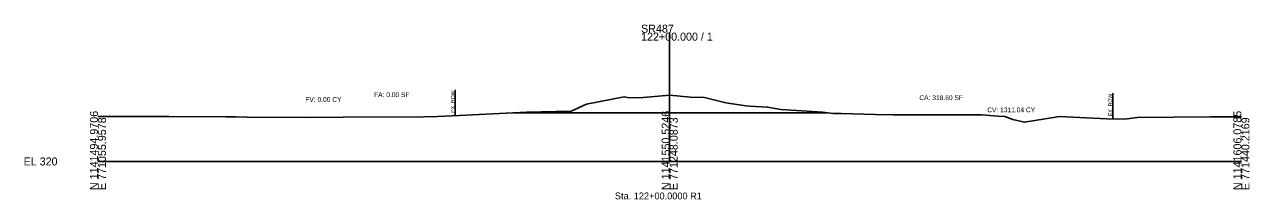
# Model space of a CAD drawing. Extents: x -26 to 5403, y -13 to 9553.
# Drawn here: x 1974.3 to 2402.8, y 1986.7 to 2047.8 of the extents above; entities that cross this region are included whole.
import ezdxf

# ---------------------------------------------------------------- set-up
doc = ezdxf.new("R2010")
doc.units = 0
for name, color, linetype in [('Default', 7, 'Continuous'), ('Draft_XS_Grid', 7, 'Continuous'), ('Draft_XS_Text', 7, 'Continuous'), ('DTM_X_GROUND', 7, 'Continuous'), ('X_ROW', 7, 'Continuous'), ('XS_CELL', 7, 'Continuous'), ('XS_M_SHAPES_EARTHWORK', 7, 'Continuous'), ('XS_P_GROUND', 7, 'Continuous'), ('XS_SHEET_EW_TX_AREA', 7, 'Continuous'), ('XS_SHEET_EW_TX_VOLUME', 7, 'Continuous')]:
    doc.layers.add(name, color=color, linetype=linetype)

msp = doc.modelspace()

# ---------------------------------------------------------------- linework, layer by layer
at = {"layer": 'Default'}
msp.add_lwpolyline([(2255.27, 2017), (2145.59, 2017)], dxfattribs=at)
at = {"layer": 'DTM_X_GROUND'}
msp.add_lwpolyline([(2000, 2015.73), (2011.96, 2015.67), (2024.75, 2015.69), (2044.77, 2015.59), (2048.4, 2015.56), (2052.22, 2015.51), (2073.02, 2015.32), (2085.71, 2015.48), (2113.96, 2015.54), (2118.81, 2015.72), (2126.35, 2016.08), (2145.19, 2016.96), (2149.92, 2017.23), (2151.07, 2017.25), (2151.34, 2017.24), (2152.46, 2017.24), (2155.1, 2017.36), (2165.52, 2017.6), (2170.92, 2020.04), (2184.07, 2022.56), (2185.86, 2022.23), (2190.68, 2022.39), (2200.11, 2023.13), (2207.28, 2022.47), (2212.23, 2022.29), (2219.66, 2020.43), (2226.67, 2019.43), (2227.9, 2019.36), (2234.26, 2018.98), (2238.93, 2018.2), (2253.62, 2017.21), (2257.2, 2016.75), (2260.16, 2016.7), (2271.9, 2016.4), (2278.19, 2016.24), (2298.79, 2016.32), (2309.05, 2016.24), (2314.77, 2015.84), (2317.21, 2015.74), (2320.02, 2014.65), (2324.12, 2013.67), (2331.37, 2014.91), (2336.43, 2015.7), (2352.97, 2014.93), (2359.19, 2014.72), (2363.57, 2015.31), (2389.17, 2015.6), (2399.77, 2015.62), (2400, 2015.62)], dxfattribs=at)
at = {"layer": 'X_ROW'}
for p, q in [((2125, 2025.02), (2125, 2016.02)), ((2355, 2023.86), (2355, 2014.86))]:
    msp.add_line(p, q, dxfattribs=at)
at = {"layer": 'XS_CELL'}
for p, q in [((2200, 2000), (2200, 2045)), ((2000, 2000), (2200, 2000)), ((2200, 2000), (2400, 2000))]:
    msp.add_line(p, q, dxfattribs=at)
at = {"layer": 'XS_M_SHAPES_EARTHWORK'}
for points in [[(2145.94, 2017), (2149.92, 2017.23), (2151.07, 2017.25), (2151.34, 2017.24), (2152.46, 2017.24), (2155.1, 2017.36), (2165.52, 2017.6), (2170.92, 2020.04), (2184.07, 2022.56), (2185.86, 2022.23), (2190.68, 2022.39), (2200.11, 2023.13), (2207.28, 2022.47), (2212.23, 2022.29), (2219.66, 2020.43), (2226.67, 2019.43), (2227.9, 2019.36), (2234.26, 2018.98), (2238.93, 2018.2), (2253.62, 2017.21), (2255.27, 2017), (2255.07, 2017), (2254.96, 2017), (2254.71, 2017), (2254.6, 2017), (2254.53, 2017), (2254.5, 2017), (2252.82, 2017), (2252.16, 2017), (2220.69, 2017), (2220.64, 2017), (2195.06, 2017), (2194.02, 2017), (2193.31, 2017), (2192.22, 2017), (2178.38, 2017), (2177.48, 2017), (2176.34, 2017), (2175.51, 2017), (2162.66, 2017), (2161.84, 2017), (2160.96, 2017), (2160.48, 2017), (2157.2, 2017), (2156.12, 2017), (2155.72, 2017), (2154.77, 2017), (2154.75, 2017), (2153.9, 2017), (2147.7, 2017), (2147.09, 2017), (2147.06, 2017), (2146.94, 2017), (2146.15, 2017), (2145.98, 2017)], [(2145.59, 2017), (2145.59, 2016.98), (2145.94, 2017)]]:
    msp.add_lwpolyline(points, close=True, dxfattribs=at)
at = {"layer": 'XS_P_GROUND'}
msp.add_lwpolyline([(2145.59, 2017), (2145.98, 2017), (2146.15, 2017), (2146.94, 2017), (2147.06, 2017), (2147.09, 2017), (2147.7, 2017), (2153.9, 2017), (2154.75, 2017), (2154.77, 2017), (2155.72, 2017), (2156.12, 2017), (2157.2, 2017), (2160.48, 2017), (2160.96, 2017), (2161.84, 2017), (2162.66, 2017), (2175.51, 2017), (2176.34, 2017), (2177.48, 2017), (2178.38, 2017), (2192.22, 2017), (2193.31, 2017), (2194.02, 2017), (2195.06, 2017), (2220.64, 2017), (2220.69, 2017), (2252.16, 2017), (2252.82, 2017), (2254.5, 2017), (2254.53, 2017), (2254.6, 2017), (2254.71, 2017), (2254.96, 2017), (2255.07, 2017), (2255.27, 2017)], dxfattribs=at)

# ---------------------------------------------------------------- texts
at = {"layer": 'Draft_XS_Grid'}
msp.add_text('-', height=0.0001, dxfattribs=at).set_placement((2000, 2000))
at = {"layer": 'Draft_XS_Text'}
msp.add_text('Sta. 122+00.0000 R1', height=2.4, dxfattribs=at).set_placement((2180.84, 1986.75))
at = {"layer": 'X_ROW'}
for p in [(2124.8, 2017.02), (2354.8, 2015.86)]:
    msp.add_text('EX. ROW', height=1.3, rotation=90, dxfattribs=at).set_placement(p)
at = {"layer": 'XS_CELL'}
for s, p in [('SR487', (2190, 2045)), ('122+00.000 / 1', (2190, 2042.2)), ('EL 320', (1974, 1998.6))]:
    msp.add_text(s, height=2.8, dxfattribs=at).set_placement(p)
for s, p in [('N 1141494.9706', (2000, 1990)), ('E 771055.9578', (2002.8, 1990)), ('N 1141550.5246', (2200, 1990)), ('E 771248.0873', (2202.8, 1990)), ('N 1141606.0785', (2400, 1990)), ('E 771440.2169', (2402.8, 1990))]:
    msp.add_text(s, height=2.8, rotation=90, dxfattribs=at).set_placement(p)
at = {"layer": 'XS_SHEET_EW_TX_AREA'}
for s, p in [('FA: 0.00 SF', (2096.6, 2022.5)), ('CA: 318.60 SF', (2287.36, 2021.44))]:
    msp.add_text(s, height=1.68, dxfattribs=at).set_placement(p)
at = {"layer": 'XS_SHEET_EW_TX_VOLUME'}
for s, p in [('FV: 0.00 CY', (2072.55, 2020.82)), ('CV: 1311.04 CY', (2311.09, 2017.18))]:
    msp.add_text(s, height=1.68, dxfattribs=at).set_placement(p)

doc.saveas('drawing.dxf')
